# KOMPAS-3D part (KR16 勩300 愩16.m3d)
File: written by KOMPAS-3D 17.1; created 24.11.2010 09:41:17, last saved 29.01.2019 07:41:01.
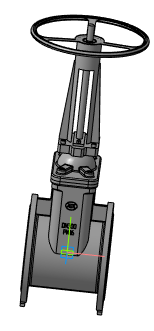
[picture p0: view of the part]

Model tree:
1. Плоскость XY
2. Плоскость ZX
3. Плоскость ZY
4. Ось X
5. Ось Y
6. Ось Z
7. Начало координат
8. Операция без истории:2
